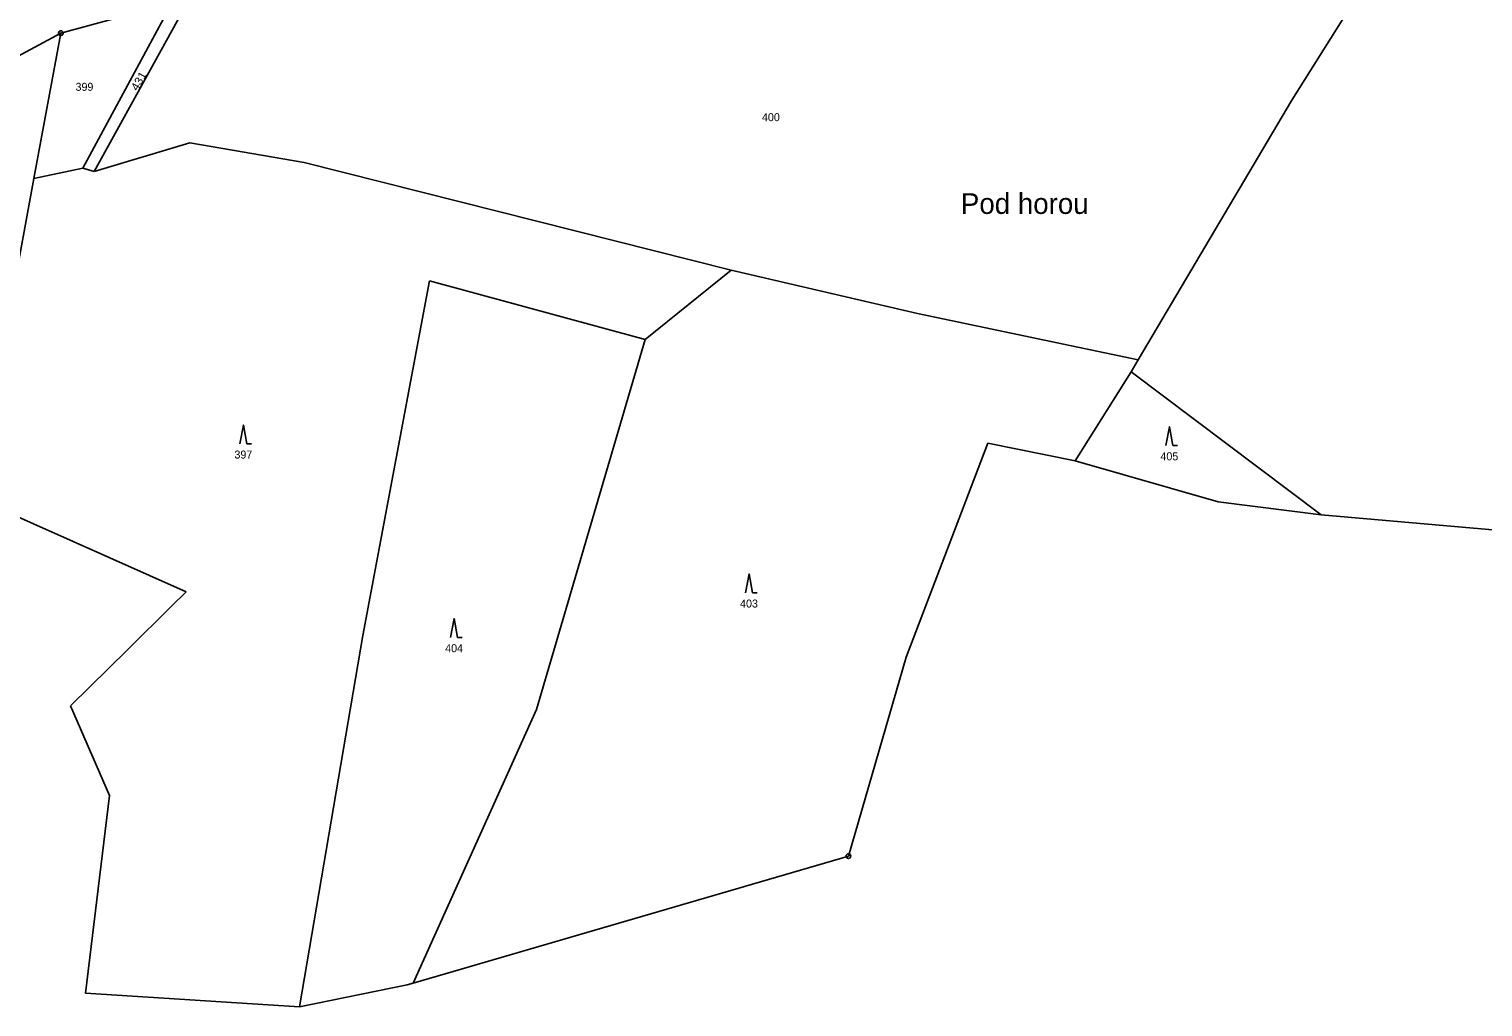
# Model space of a CAD drawing. Extents: x -791548 to -789311, y -1142631 to -1140855.
# Drawn here: x -790753.3 to -790444.3, y -1142554.6 to -1142346.8 of the extents above; entities that cross this region are included whole.
import ezdxf
from ezdxf.enums import TextEntityAlignment as Align

# ---------------------------------------------------------------- set-up
doc = ezdxf.new("R2010")
doc.units = 0
doc.header["$LTSCALE"] = 0.68
for name, color, linetype, lineweight in [('1', 7, 'Continuous', 25), ('3', 7, 'Continuous', 25), ('7', 7, 'Continuous', 13), ('8', 7, 'Continuous', 25)]:
    doc.layers.add(name, color=color, linetype=linetype, lineweight=lineweight)
doc.layers.add('2', color=7, linetype='Continuous')

msp = doc.modelspace()

# ---------------------------------------------------------------- linework, layer by layer
at = {"layer": '1'}
for p, q in [((-790484.92, -1142361.93), (-790464.91, -1142330.08)), ((-790722.73, -1142340.96), (-790741.85, -1142376.38)), ((-790746.5, -1142347.69), (-790734.28, -1142344.35)), ((-790739.43, -1142377.07), (-790720.3, -1142342.48)), ((-790756.66, -1142353.16), (-790746.5, -1142347.69)), ((-790746.5, -1142347.69), (-790752.27, -1142378.61)), ((-790484.92, -1142361.93), (-790517.6, -1142417.16)), ((-790739.43, -1142377.07), (-790719.08, -1142371.04)), ((-790719.08, -1142371.04), (-790694.83, -1142375.18)), ((-790694.83, -1142375.18), (-790604.1, -1142398.07)), ((-790758.06, -1142410.4), (-790752.27, -1142378.61)), ((-790752.27, -1142378.61), (-790741.85, -1142376.38)), ((-790741.85, -1142376.38), (-790739.43, -1142377.07)), ((-790682.34, -1142475.69), (-790668.18, -1142400.35)), ((-790668.18, -1142400.35), (-790622.35, -1142412.79)), ((-790604.1, -1142398.07), (-790622.35, -1142412.79)), ((-790564.45, -1142407.25), (-790604.1, -1142398.07)), ((-790517.6, -1142417.16), (-790564.45, -1142407.25)), ((-790622.35, -1142412.79), (-790645.42, -1142491.46)), ((-790519.06, -1142419.67), (-790517.6, -1142417.16)), ((-790519.06, -1142419.67), (-790530.94, -1142438.56)), ((-790478.69, -1142450.06), (-790519.06, -1142419.67)), ((-790549.54, -1142434.87), (-790566.88, -1142480.31)), ((-790530.94, -1142438.56), (-790549.54, -1142434.87)), ((-790500.57, -1142447.33), (-790530.94, -1142438.56)), ((-790719.86, -1142466.43), (-790764.75, -1142446.47)), ((-790478.69, -1142450.06), (-790500.57, -1142447.33)), ((-790436.94, -1142453.75), (-790478.69, -1142450.06)), ((-790722.98, -1142469.5), (-790719.86, -1142466.43)), ((-790732.31, -1142478.71), (-790722.98, -1142469.5)), ((-790695.81, -1142554.65), (-790682.34, -1142475.69)), ((-790744.45, -1142490.68), (-790732.31, -1142478.71)), ((-790566.88, -1142480.31), (-790579.17, -1142522.61)), ((-790736.18, -1142509.75), (-790744.45, -1142490.68)), ((-790645.42, -1142491.46), (-790671.65, -1142549.58)), ((-790579.17, -1142522.61), (-790671.65, -1142549.58)), ((-790672.89, -1142549.94), (-790695.81, -1142554.65)), ((-790671.65, -1142549.58), (-790672.89, -1142549.94))]:
    msp.add_line(p, q, dxfattribs=at)
msp.add_lwpolyline([(-790695.81, -1142554.65), (-790741.3, -1142551.72), (-790736.18, -1142509.75)], dxfattribs=at)
at = {"layer": '3'}
for p, q in [((-790706.98, -1142434.98), (-790705.984, -1142434.98)), ((-790510.21, -1142435.35), (-790509.214, -1142435.35)), ((-790599.53, -1142466.64), (-790598.534, -1142466.64)), ((-790662.2, -1142476.13), (-790661.204, -1142476.13))]:
    msp.add_line(p, q, dxfattribs=at)
for points in [[(-790706.98, -1142434.98), (-790707.73, -1142430.98), (-790708.48, -1142434.98)], [(-790510.21, -1142435.35), (-790510.96, -1142431.35), (-790511.71, -1142435.35)], [(-790599.53, -1142466.64), (-790600.28, -1142462.64), (-790601.03, -1142466.64)], [(-790662.2, -1142476.13), (-790662.95, -1142472.13), (-790663.7, -1142476.13)]]:
    msp.add_lwpolyline(points, dxfattribs=at)
at = {"layer": '8'}
for centre, radius in [((-790746.4999, -1142347.69), 0.5), ((-790746.4999, -1142347.69), 0.0303), ((-790579.17, -1142522.6099), 0.5), ((-790579.17, -1142522.6099), 0.0303)]:
    msp.add_circle(centre, radius, dxfattribs=at)

# ---------------------------------------------------------------- texts
at = {"layer": '2', "width": 1.1}
msp.add_text('431', height=1.7, rotation=60, dxfattribs=at).set_placement((-790729.2236, -1142358.294), align=Align.CENTER)
at = {"layer": '2'}
for s, p in [('399', (-790741.499, -1142359.952)), ('400', (-790595.629, -1142366.412)), ('397', (-790707.729, -1142438.112)), ('405', (-790510.959, -1142438.482)), ('403', (-790600.279, -1142469.772)), ('404', (-790662.949, -1142479.262))]:
    msp.add_text(s, height=1.7, dxfattribs=at).set_placement(p, align=Align.CENTER)
at = {"layer": '7'}
msp.add_text('Pod horou', height=4.4, dxfattribs=at).set_placement((-790555.26, -1142386.12))

doc.saveas('drawing.dxf')
